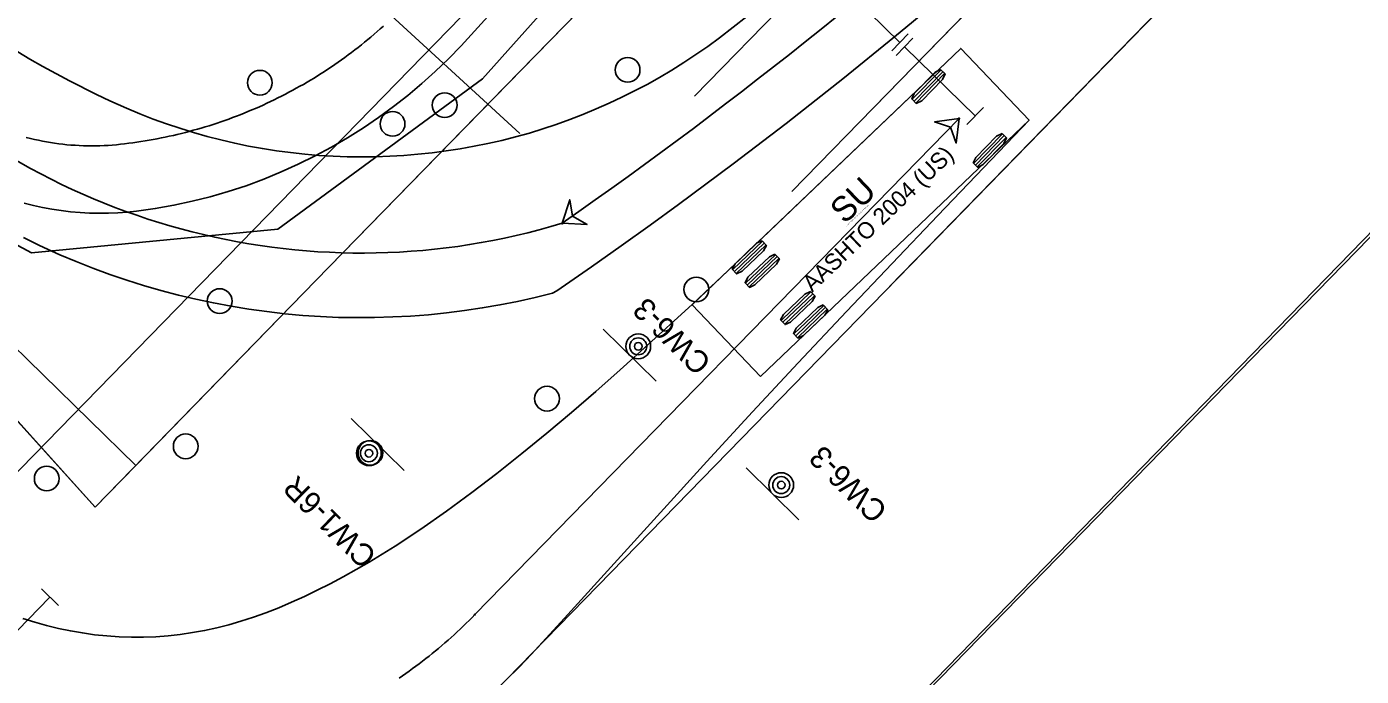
# Model space of a CAD drawing. Extents: x 2252379 to 2256472, y 13788212 to 13792539.
# Drawn here: x 2255447.1 to 2255554.9, y 13791315.2 to 13791367.7 of the extents above; entities that cross this region are included whole.
import ezdxf

# ---------------------------------------------------------------- set-up
doc = ezdxf.new("R2010")
doc.units = 0
for name, color, linetype in [('D_DRN_AREA_X', 7, 'Continuous'), ('D_TCP_OVERALL_PATT', 7, 'Continuous'), ('D_TCP_PH_1_ATVEHICLE', 7, 'Continuous'), ('D_TCP_PH_1_BARRIER', 7, 'Continuous'), ('D_TCP_PH_1_PATT', 7, 'Continuous'), ('D_TCP_PH_1A_ATVEHICLE', 7, 'Continuous'), ('D_TCP_PH_1A_BARREL', 7, 'Continuous'), ('D_TCP_PH_1A_SIGN', 7, 'Continuous'), ('D_TCP_PH_1A_WZPM_NRMV_4IN_W_SLD', 7, 'Continuous'), ('D_TCP_PH_1A_WZPM_RMV_4IN_Y_SLD', 7, 'Continuous'), ('D_TCP_PH_1B_BARREL', 7, 'Continuous'), ('D_TCP_PH_1B_PATT', 7, 'Continuous'), ('D_TCP_PH_1B_SIGN', 7, 'Continuous'), ('D_TCP_PH_1B_WZPM_NRMV_4IN_W_SLD', 7, 'Continuous'), ('D_TCP_PH_1B_WZPM_RMV_4IN_Y_SLD', 7, 'Continuous'), ('D_TCP_PH_2_BARREL', 7, 'Continuous'), ('D_TCP_PH_2_MISC', 7, 'Continuous'), ('D_TCP_PH_2_WZPM_NRMV_4IN_W_SLD', 7, 'Continuous'), ('D_TCP_PH_2A_WZPM_NRMV_4IN_W_SLD', 7, 'Continuous'), ('D_TCP_PH_2A_WZPM_RMV_4IN_Y_SLD', 7, 'Continuous'), ('E_Structure_Sign_Sign And Post Single_SGN', 7, 'Continuous'), ('Level 1', 7, 'Continuous'), ('SIGN_DESCR', 7, 'Continuous')]:
    doc.layers.add(name, color=color, linetype=linetype)

# ---------------------------------------------------------------- blocks, each defined once
blk = doc.blocks.new('TYP3')
at = {"layer": 'Level 1'}
for p, q in [((-0.1651, 0.0395), (-0.1651, -0.0395)), ((0.163, 0), (-0.163, 0)), ((0.163, 0.0395), (0.163, -0.0395))]:
    blk.add_line(p, q, dxfattribs=at)
blk = doc.blocks.new('SGN')
at = {"layer": 'E_Structure_Sign_Sign And Post Single_SGN'}
blk.add_line((0.6, -0.2), (-0.6, -0.2), dxfattribs=at)
for radius in [0.2, 0.137, 0.0611]:
    blk.add_circle((0, 0), radius, dxfattribs=at)

msp = doc.modelspace()

# ---------------------------------------------------------------- linework, layer by layer
at = {"layer": 'D_DRN_AREA_X'}
msp.add_line((2255454.02, 13791389.24), (2255486.93, 13791359.06), dxfattribs=at)
at = {"layer": 'D_TCP_OVERALL_PATT'}
for p, q in [((2255721.86, 13791604.85), (2255480.34, 13791357.3)), ((2255483.41, 13791360.45), (2255721.86, 13791604.85)), ((2255483.41, 13791360.45), (2255503.41, 13791380.95)), ((2255470.46, 13791347.18), (2255483.41, 13791360.45)), ((2255470.46, 13791347.18), (2255483.41, 13791360.45)), ((2255480.34, 13791357.3), (2255470.46, 13791347.18)), ((2255430.4, 13791357.14), (2255455.9, 13791332.26)), ((2255430.4, 13791357.14), (2255455.9, 13791332.26)), ((2255455.9, 13791332.26), (2255470.46, 13791347.18)), ((2255455.9, 13791332.26), (2255470.46, 13791347.18))]:
    msp.add_line(p, q, dxfattribs=at)
for points in [[(2255104.28, 13790888.18), (2255118.36, 13790881.14), (2255128.85, 13790888.25), (2255137.45, 13790895.94), (2255142.38, 13790905.75), (2255131.78, 13790916.36), (2255285.15, 13791073.53), (2255300.44, 13791089.2), (2255318.42, 13791107.62), (2255362.49, 13791152.79), (2255763.39, 13791564.32)], [(2255452.62, 13791328.89), (2255426.07, 13791358.25), (2255426.42, 13791358.62), (2255427.07, 13791359.61), (2255427.4, 13791360.65), (2255427.43, 13791362.12), (2255426.94, 13791363.99), (2255414.49, 13791377.76), (2255409.1, 13791383.33), (2255393.54, 13791398.31)], [(2255470.46, 13791347.18), (2255455.9, 13791332.26), (2255452.62, 13791328.89)]]:
    msp.add_lwpolyline(points, dxfattribs=at)
at = {"layer": 'D_TCP_PH_1_ATVEHICLE'}
for points in [[(2255487.02, 13791371.45), (2255482.18, 13791366.12), (2255481.16, 13791365.08), (2255480.1, 13791364.06), (2255479.01, 13791363.08), (2255477.88, 13791362.13), (2255476.72, 13791361.22), (2255475.52, 13791360.34), (2255474.29, 13791359.51), (2255473.02, 13791358.71), (2255471.72, 13791357.95), (2255470.39, 13791357.24), (2255469.03, 13791356.57), (2255467.65, 13791355.95), (2255466.24, 13791355.37), (2255464.81, 13791354.84), (2255463.36, 13791354.37), (2255461.91, 13791353.95), (2255460.45, 13791353.58), (2255458.98, 13791353.26), (2255457.48, 13791352.99), (2255455.97, 13791352.77), (2255455.21, 13791352.69), (2255454.45, 13791352.64), (2255453.69, 13791352.61), (2255452.93, 13791352.61), (2255452.16, 13791352.63), (2255451.4, 13791352.67), (2255450.64, 13791352.74), (2255449.89, 13791352.83), (2255449.13, 13791352.95), (2255448.38, 13791353.08), (2255447.64, 13791353.24), (2255446.9, 13791353.43)], [(2255447.06, 13791358.74), (2255447.39, 13791358.66), (2255447.71, 13791358.58), (2255448.04, 13791358.51), (2255448.36, 13791358.44), (2255448.69, 13791358.38), (2255449.02, 13791358.33), (2255449.35, 13791358.28), (2255449.68, 13791358.23), (2255450.01, 13791358.19), (2255450.34, 13791358.15), (2255450.67, 13791358.12), (2255451.01, 13791358.1), (2255451.34, 13791358.08), (2255451.67, 13791358.06), (2255452.01, 13791358.05), (2255452.34, 13791358.05), (2255452.67, 13791358.05), (2255453.01, 13791358.06), (2255453.34, 13791358.07), (2255453.67, 13791358.09), (2255454, 13791358.11), (2255454.34, 13791358.14), (2255454.67, 13791358.18), (2255455, 13791358.22), (2255455.33, 13791358.26), (2255455.66, 13791358.3), (2255455.99, 13791358.35), (2255456.32, 13791358.4), (2255456.65, 13791358.45), (2255456.98, 13791358.51), (2255457.31, 13791358.57), (2255457.63, 13791358.63), (2255457.96, 13791358.69), (2255458.29, 13791358.76), (2255458.61, 13791358.83), (2255458.94, 13791358.9), (2255459.26, 13791358.98), (2255459.59, 13791359.05), (2255459.91, 13791359.14), (2255460.23, 13791359.22), (2255460.55, 13791359.31), (2255460.88, 13791359.4), (2255461.2, 13791359.49), (2255461.51, 13791359.58), (2255461.83, 13791359.68), (2255462.15, 13791359.78), (2255462.47, 13791359.89), (2255462.78, 13791359.99), (2255463.1, 13791360.1), (2255463.41, 13791360.22), (2255463.73, 13791360.33), (2255464.04, 13791360.45), (2255464.35, 13791360.57), (2255464.66, 13791360.69), (2255464.97, 13791360.82), (2255465.27, 13791360.95), (2255465.58, 13791361.08), (2255465.89, 13791361.21), (2255466.19, 13791361.35), (2255466.49, 13791361.49), (2255466.79, 13791361.63), (2255467.09, 13791361.77), (2255467.39, 13791361.92), (2255467.69, 13791362.07), (2255467.99, 13791362.22), (2255468.28, 13791362.38), (2255468.58, 13791362.54), (2255468.87, 13791362.7), (2255469.16, 13791362.86), (2255469.45, 13791363.02), (2255469.74, 13791363.19), (2255470.02, 13791363.36), (2255470.31, 13791363.53), (2255470.59, 13791363.71), (2255470.87, 13791363.89), (2255471.16, 13791364.07), (2255471.43, 13791364.25), (2255471.71, 13791364.44), (2255471.99, 13791364.62), (2255472.26, 13791364.81), (2255472.53, 13791365.01), (2255472.8, 13791365.2), (2255473.07, 13791365.4), (2255473.34, 13791365.6), (2255473.6, 13791365.8), (2255473.87, 13791366), (2255474.13, 13791366.21), (2255474.39, 13791366.42), (2255474.65, 13791366.63), (2255474.9, 13791366.84), (2255475.16, 13791367.06), (2255475.41, 13791367.28), (2255475.66, 13791367.5), (2255475.91, 13791367.72)]]:
    msp.add_lwpolyline(points, dxfattribs=at)
at = {"layer": 'D_TCP_PH_1_BARRIER'}
msp.add_line((2255483.91, 13791363.47), (2255497.24, 13791378.38), dxfattribs=at)
msp.add_lwpolyline([(2255429.85, 13791358.86), (2255447.49, 13791349.42), (2255467.39, 13791351.32), (2255483.91, 13791363.47)], dxfattribs=at)
at = {"layer": 'D_TCP_PH_1_PATT'}
for p, q in [((2255721.86, 13791604.85), (2255480.34, 13791357.3)), ((2255480.34, 13791357.3), (2255470.46, 13791347.18))]:
    msp.add_line(p, q, dxfattribs=at)
for points in [[(2255091.3, 13790894.58), (2255104.25, 13790888.15), (2255118.36, 13790881.14), (2255128.85, 13790888.25), (2255137.45, 13790895.94), (2255142.38, 13790905.75), (2255131.78, 13790916.36), (2255295.32, 13791083.95), (2255307.58, 13791096.52), (2255322.25, 13791111.55), (2255663.82, 13791461.58), (2255763.39, 13791564.32)], [(2255452.62, 13791328.89), (2255422.61, 13791362.07), (2255423.1, 13791362.61), (2255423.52, 13791363.44), (2255423.66, 13791364.23), (2255423.59, 13791364.98), (2255422.85, 13791366.41), (2255405.06, 13791385.48), (2255398.07, 13791392.17), (2255392.23, 13791397.58)], [(2255470.46, 13791347.18), (2255455.9, 13791332.26), (2255452.62, 13791328.89)]]:
    msp.add_lwpolyline(points, dxfattribs=at)
at = {"layer": 'D_TCP_PH_1A_ATVEHICLE'}
for p, q in [((2255522.56, 13791365.92), (2255500.85, 13791345.22)), ((2255528.08, 13791360.14), (2255522.56, 13791365.92)), ((2255522.56, 13791365.92), (2255522.56, 13791365.92)), ((2255520.96, 13791364.19), (2255518.63, 13791361.81)), ((2255521.1, 13791364.04), (2255518.78, 13791361.66)), ((2255521.25, 13791363.9), (2255518.92, 13791361.51)), ((2255483.3, 13791320.22), (2255522.42, 13791360.27)), ((2255506.37, 13791339.43), (2255528.08, 13791360.14)), ((2255525.92, 13791359.02), (2255523.59, 13791356.64)), ((2255526.07, 13791358.88), (2255523.74, 13791356.49)), ((2255526.22, 13791358.73), (2255523.89, 13791356.35)), ((2255506.54, 13791350.36), (2255504.13, 13791348.06)), ((2255506.68, 13791350.21), (2255504.27, 13791347.91)), ((2255506.83, 13791350.06), (2255504.42, 13791347.76)), ((2255507.58, 13791349.27), (2255505.16, 13791346.97)), ((2255507.72, 13791349.12), (2255505.31, 13791346.82)), ((2255507.86, 13791348.97), (2255505.45, 13791346.67)), ((2255510.45, 13791346.26), (2255508.04, 13791343.96)), ((2255510.6, 13791346.11), (2255508.18, 13791343.81)), ((2255510.74, 13791345.96), (2255508.33, 13791343.66)), ((2255500.85, 13791345.22), (2255506.37, 13791339.43)), ((2255511.49, 13791345.17), (2255509.08, 13791342.87)), ((2255511.63, 13791345.02), (2255509.22, 13791342.72)), ((2255511.77, 13791344.87), (2255509.36, 13791342.57))]:
    msp.add_line(p, q, dxfattribs=at)
for points in [[(2255521.34, 13791370.31), (2255517.21, 13791366.86), (2255513.02, 13791363.46), (2255510.87, 13791361.76), (2255508.44, 13791359.86), (2255504.18, 13791356.61), (2255499.75, 13791353.32), (2255497.46, 13791351.66), (2255495.12, 13791349.99), (2255492.71, 13791348.3), (2255489.91, 13791346.36), (2255489.58, 13791346.17), (2255488.17, 13791345.82), (2255486.75, 13791345.5), (2255485.32, 13791345.22), (2255483.89, 13791344.97), (2255482.45, 13791344.75), (2255481.01, 13791344.57), (2255479.56, 13791344.42), (2255478.11, 13791344.31), (2255476.66, 13791344.24), (2255475.2, 13791344.19), (2255473.75, 13791344.19), (2255472.29, 13791344.21), (2255470.84, 13791344.27), (2255469.39, 13791344.37), (2255467.94, 13791344.5), (2255466.49, 13791344.67), (2255465.05, 13791344.87), (2255463.61, 13791345.1), (2255462.18, 13791345.37), (2255460.76, 13791345.67), (2255459.35, 13791346.01), (2255457.94, 13791346.38), (2255456.54, 13791346.78), (2255455.17, 13791347.21), (2255453.8, 13791347.68), (2255452.44, 13791348.18), (2255451.1, 13791348.71), (2255449.78, 13791349.26), (2255448.13, 13791350.01), (2255446.82, 13791350.65)], [(2255445.26, 13791366.33), (2255447.35, 13791365.06), (2255448.4, 13791364.45), (2255450.55, 13791363.29), (2255452.72, 13791362.2), (2255453.81, 13791361.69), (2255455.16, 13791361.09), (2255456.22, 13791360.64), (2255457.3, 13791360.22), (2255458.38, 13791359.83), (2255459.46, 13791359.47), (2255460.57, 13791359.13), (2255461.67, 13791358.82), (2255462.78, 13791358.53), (2255463.9, 13791358.27), (2255465.02, 13791358.04), (2255466.14, 13791357.83), (2255467.28, 13791357.66), (2255468.41, 13791357.51), (2255469.55, 13791357.38), (2255470.69, 13791357.28), (2255471.84, 13791357.21), (2255472.98, 13791357.17), (2255474.13, 13791357.16), (2255475.27, 13791357.17), (2255476.42, 13791357.21), (2255477.56, 13791357.28), (2255478.7, 13791357.37), (2255479.84, 13791357.49), (2255480.98, 13791357.64), (2255482.11, 13791357.81), (2255483.24, 13791358.02), (2255484.36, 13791358.25), (2255485.48, 13791358.5), (2255486.59, 13791358.78), (2255487.7, 13791359.09), (2255488.79, 13791359.43), (2255489.88, 13791359.79), (2255490.96, 13791360.18), (2255492.03, 13791360.59), (2255493.09, 13791361.03), (2255494.14, 13791361.49), (2255495.18, 13791361.98), (2255496.2, 13791362.49), (2255497.21, 13791363.02), (2255498.22, 13791363.58), (2255499.21, 13791364.17), (2255500.18, 13791364.78), (2255501.15, 13791365.42), (2255502.11, 13791366.08), (2255503.06, 13791366.77), (2255505.28, 13791368.49)], [(2255446.79, 13791319.91), (2255447.74, 13791319.61), (2255448.69, 13791319.34), (2255449.66, 13791319.1), (2255450.63, 13791318.9), (2255451.6, 13791318.73), (2255452.58, 13791318.59), (2255453.57, 13791318.49), (2255454.56, 13791318.42), (2255455.55, 13791318.39), (2255456.54, 13791318.4), (2255457.53, 13791318.43), (2255458.52, 13791318.51), (2255459.5, 13791318.61), (2255460.48, 13791318.76), (2255461.46, 13791318.93), (2255462.44, 13791319.14), (2255463.41, 13791319.39), (2255464.4, 13791319.68), (2255465.41, 13791320.01), (2255466.42, 13791320.37), (2255467.45, 13791320.77), (2255468.48, 13791321.21), (2255469.53, 13791321.68), (2255470.57, 13791322.18), (2255471.62, 13791322.71), (2255472.67, 13791323.27), (2255473.72, 13791323.85), (2255474.76, 13791324.46), (2255476.85, 13791325.75), (2255478.93, 13791327.12), (2255481, 13791328.56), (2255483.05, 13791330.06), (2255485.08, 13791331.61), (2255487.1, 13791333.22), (2255489.11, 13791334.86), (2255491.1, 13791336.53), (2255493.07, 13791338.23), (2255495.04, 13791339.97), (2255496.99, 13791341.72), (2255500.87, 13791345.28), (2255504.72, 13791348.91), (2255522.56, 13791365.92), (2255528.08, 13791360.14), (2255520.69, 13791352.44), (2255513.33, 13791344.69), (2255509.42, 13791340.53), (2255505.74, 13791336.57), (2255502.05, 13791332.57), (2255490.81, 13791320.22), (2255487.88, 13791317.02), (2255486.87, 13791315.97), (2255485.82, 13791314.94)], [(2255522.42, 13791360.27), (2255520.44, 13791359.99), (2255521.73, 13791359.55), (2255522.19, 13791358.28), (2255522.42, 13791360.27)], [(2255490.36, 13791351.8), (2255492.36, 13791351.71), (2255491.18, 13791352.38), (2255490.96, 13791353.71), (2255490.36, 13791351.8)], [(2255477.18, 13791315.09), (2255477.45, 13791315.28), (2255477.73, 13791315.47), (2255478, 13791315.66), (2255478.27, 13791315.86), (2255478.54, 13791316.05), (2255478.81, 13791316.25), (2255479.07, 13791316.45), (2255479.34, 13791316.66), (2255479.6, 13791316.86), (2255479.86, 13791317.07), (2255480.12, 13791317.28), (2255480.37, 13791317.49), (2255480.63, 13791317.71), (2255480.88, 13791317.93), (2255481.13, 13791318.15), (2255481.38, 13791318.37), (2255481.63, 13791318.59), (2255481.87, 13791318.82), (2255482.11, 13791319.05), (2255482.36, 13791319.28), (2255482.59, 13791319.51), (2255482.83, 13791319.74), (2255483.07, 13791319.98), (2255483.3, 13791320.22)]]:
    msp.add_lwpolyline(points, dxfattribs=at)
for points in [[(2255520.92, 13791364.23), (2255521.29, 13791363.86), (2255521.08, 13791363.42), (2255519.4, 13791361.7), (2255518.96, 13791361.48), (2255518.59, 13791361.84), (2255518.8, 13791362.28), (2255520.48, 13791364)], [(2255522.42, 13791360.27), (2255520.44, 13791359.99), (2255521.73, 13791359.55), (2255522.19, 13791358.28)], [(2255525.89, 13791359.06), (2255526.26, 13791358.7), (2255526.04, 13791358.25), (2255524.37, 13791356.54), (2255523.93, 13791356.31), (2255523.56, 13791356.68), (2255523.77, 13791357.12), (2255525.45, 13791358.84)], [(2255490.36, 13791351.8), (2255492.36, 13791351.71), (2255491.18, 13791352.38), (2255490.96, 13791353.71)], [(2255506.5, 13791350.4), (2255506.86, 13791350.02), (2255506.63, 13791349.59), (2255504.9, 13791347.93), (2255504.45, 13791347.72), (2255504.09, 13791348.1), (2255504.32, 13791348.53), (2255506.06, 13791350.19)], [(2255507.54, 13791349.31), (2255507.9, 13791348.94), (2255507.67, 13791348.5), (2255505.93, 13791346.84), (2255505.49, 13791346.63), (2255505.13, 13791347.01), (2255505.36, 13791347.45), (2255507.09, 13791349.1)], [(2255510.42, 13791346.3), (2255510.78, 13791345.92), (2255510.55, 13791345.48), (2255508.81, 13791343.83), (2255508.36, 13791343.62), (2255508, 13791344), (2255508.23, 13791344.43), (2255509.97, 13791346.09)], [(2255511.45, 13791345.21), (2255511.81, 13791344.83), (2255511.58, 13791344.4), (2255509.84, 13791342.74), (2255509.4, 13791342.53), (2255509.04, 13791342.91), (2255509.27, 13791343.35), (2255511.01, 13791345)]]:
    msp.add_lwpolyline(points, close=True, dxfattribs=at)
for centre in [(2255522.42, 13791360.27), (2255490.36, 13791351.8), (2255490.36, 13791351.8), (2255483.3, 13791320.22), (2255483.3, 13791320.22)]:
    msp.add_circle(centre, 0.0417, dxfattribs=at)
for centre, radius, start, end in [((2255271.35, 13791665.9), 382.91, 304.8869, 312.7091), ((2255474.16, 13791405.17), 55.77, 224.6741, 286.8877)]:
    msp.add_arc(centre, radius, start, end, dxfattribs=at)
at = {"layer": 'D_TCP_PH_1A_BARREL'}
for centre in [(2255495.64, 13791364.19), (2255495.64, 13791364.19), (2255465.93, 13791363.15), (2255465.93, 13791363.15), (2255480.86, 13791361.34), (2255480.86, 13791361.34), (2255501.19, 13791346.46), (2255501.19, 13791346.46), (2255489.13, 13791337.65), (2255489.13, 13791337.65), (2255459.94, 13791333.8), (2255459.94, 13791333.8), (2255474.86, 13791333.27), (2255474.86, 13791333.27)]:
    msp.add_circle(centre, 1, dxfattribs=at)
at = {"layer": 'D_TCP_PH_1A_WZPM_NRMV_4IN_W_SLD'}
msp.add_line((2255516.79, 13791346.7), (2255746.09, 13791581.7), dxfattribs=at)
at = {"layer": 'D_TCP_PH_1A_WZPM_RMV_4IN_Y_SLD'}
msp.add_line((2255508.92, 13791354.38), (2255737.7, 13791588.84), dxfattribs=at)
at = {"layer": 'D_TCP_PH_1B_BARREL'}
for centre in [(2255495.64, 13791364.19), (2255465.93, 13791363.15), (2255480.86, 13791361.34), (2255501.19, 13791346.46), (2255489.13, 13791337.65), (2255459.94, 13791333.8), (2255474.86, 13791333.27)]:
    msp.add_circle(centre, 1, dxfattribs=at)
at = {"layer": 'D_TCP_PH_1B_PATT'}
for p, q in [((2255483.41, 13791360.45), (2255503.41, 13791380.95)), ((2255422.61, 13791362.07), (2255452.62, 13791328.89)), ((2255470.46, 13791347.18), (2255483.41, 13791360.45)), ((2255452.62, 13791328.89), (2255470.46, 13791347.18))]:
    msp.add_line(p, q, dxfattribs=at)
at = {"layer": 'D_TCP_PH_1B_SIGN'}
msp.add_circle((2255474.86, 13791333.27), 1, dxfattribs=at)
at = {"layer": 'D_TCP_PH_1B_WZPM_NRMV_4IN_W_SLD'}
for p, q in [((2255501.04, 13791362.06), (2255729.3, 13791595.99)), ((2255516.79, 13791346.7), (2255746.09, 13791581.7))]:
    msp.add_line(p, q, dxfattribs=at)
at = {"layer": 'D_TCP_PH_1B_WZPM_RMV_4IN_Y_SLD'}
msp.add_line((2255508.92, 13791354.38), (2255737.7, 13791588.84), dxfattribs=at)
at = {"layer": 'D_TCP_PH_2_BARREL'}
for centre in [(2255476.65, 13791359.83), (2255462.68, 13791345.52), (2255448.71, 13791331.2)]:
    msp.add_circle(centre, 1, dxfattribs=at)
at = {"layer": 'D_TCP_PH_2_WZPM_NRMV_4IN_W_SLD'}
msp.add_lwpolyline([(2255420.4, 13791305.16), (2255629.91, 13791519.88)], dxfattribs=at)
at = {"layer": 'D_TCP_PH_2A_WZPM_NRMV_4IN_W_SLD'}
msp.add_lwpolyline([(2255449.01, 13791277.23), (2255658.53, 13791491.94)], dxfattribs=at)
at = {"layer": 'D_TCP_PH_2A_WZPM_RMV_4IN_Y_SLD'}
msp.add_lwpolyline([(2255515.57, 13791361.19), (2255650.65, 13791499.63)], dxfattribs=at)

# ---------------------------------------------------------------- block references
at = {"layer": 'D_TCP_PH_1A_SIGN'}
for p, xscale, yscale, rotation in [((2255474.74, 13791333.24), 5, 5.000000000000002, 135.4039053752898), ((2255508.05, 13791330.67), 5.000000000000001, 5.000000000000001, -44.59609462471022)]:
    msp.add_blockref('SGN', p, dxfattribs=dict(at, xscale=xscale, yscale=yscale, rotation=rotation))
at = {"layer": 'D_TCP_PH_1B_SIGN', "xscale": 5.000000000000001, "yscale": 5.000000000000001, "rotation": -44.59609462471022}
msp.add_blockref('SGN', (2255496.5, 13791341.87), dxfattribs=at)
at = {"layer": 'D_TCP_PH_2_MISC', "xscale": 24.384167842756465, "yscale": 24.384167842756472}
for p, rotation in [((2255514.8, 13791369.18), -44.28207184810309), ((2255520.88, 13791363.24), -44.28207184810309), ((2255446.16, 13791318.75), -134.28207184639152)]:
    msp.add_blockref('TYP3', p, dxfattribs=dict(at, rotation=rotation))

# ---------------------------------------------------------------- texts
at = {"layer": 'D_TCP_PH_1A_ATVEHICLE'}
for s, height, p in [('AASHTO 2004 (US)', 1.3333, (2255510.56, 13791346.18)), ('SU', 2, (2255513.18, 13791351.68)), ('(c) 2020 Transoft Solutions, Inc. All rights reserved.', 0.08, (2255513.31, 13791351.52))]:
    msp.add_text(s, height=height, rotation=43.6466, dxfattribs=at).set_placement(p)
at = {"layer": 'SIGN_DESCR'}
for s, p in [('CW6-3', (2255502.51, 13791340.68)), ('CW6-3', (2255516.75, 13791328.73)), ('CW1-6R', (2255475.48, 13791325.08))]:
    msp.add_text(s, height=1.8, rotation=135.4039, dxfattribs=at).set_placement(p)

doc.saveas('drawing.dxf')
